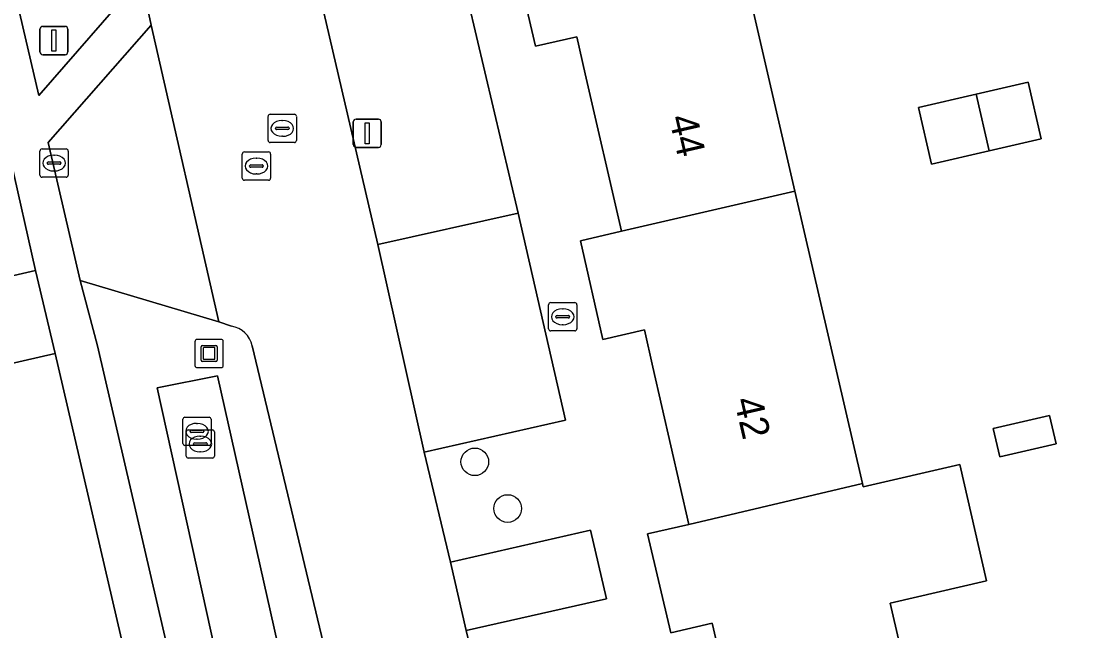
# Model space of a CAD drawing. Extents: x 156412 to 157779, y 382335 to 383768.
# Drawn here: x 156911.01 to 156948.58, y 382902.2 to 382923.76 of the extents above; entities that cross this region are included whole.
import ezdxf

# ---------------------------------------------------------------- set-up
doc = ezdxf.new("R2010")
doc.units = 0
for name, color, linetype in [('IMGEO_Berm_groen', 7, 'Continuous'), ('IMGEO_Boom', 7, 'Continuous'), ('IMGEO_Brandkraan', 7, 'Continuous'), ('IMGEO_Erf', 7, 'Continuous'), ('IMGEO_Greppel_droge_sloot', 7, 'Continuous'), ('IMGEO_Kolk', 7, 'Continuous'), ('IMGEO_Kunstobject', 7, 'Continuous'), ('IMGEO_Lichtmast', 7, 'Continuous'), ('IMGEO_Pand', 7, 'Continuous'), ('IMGEO_Pand_nummerreeks', 7, 'Continuous'), ('IMGEO_Parkeervlak_open', 7, 'Continuous'), ('IMGEO_Rijbaan_lokaal_gesloten', 7, 'Continuous'), ('IMGEO_Rijbaan_lokaal_open', 7, 'Continuous'), ('IMGEO_Rioolput', 7, 'Continuous'), ('IMGEO_Verkeersbordpaal', 7, 'Continuous'), ('IMGEO_Voetpad_open', 7, 'Continuous')]:
    doc.layers.add(name, color=color, linetype=linetype)

msp = doc.modelspace()

# ---------------------------------------------------------------- linework, layer by layer
at = {"layer": 'IMGEO_Berm_groen'}
for points in [[(156911.7, 382945.268), (156910.613, 382951.316), (156910.458, 382952.176), (156904.698, 382950.847), (156911.631, 382921.128), (156915.25, 382925.291), (156915.615, 382925.675)], [(156918.446, 382912.971), (156917.996, 382913.122), (156913.092, 382914.594), (156913.71, 382912.282), (156918.396, 382892.022), (156918.921, 382892.119), (156921.287, 382881.92), (156920.762, 382881.795), (156925.852, 382859.789), (156930.181, 382860.808)], [(156922.418, 382898.725), (156919.179, 382912.277)]]:
    msp.add_lwpolyline(points, dxfattribs=at)
for points in [[(156926.514, 382925.73), (156921.59, 382924.592), (156923.616, 382915.861), (156928.578, 382916.965)], [(156928.493, 382863.788), (156926.278, 382863.313), (156915.815, 382910.793), (156917.946, 382911.213), (156924.219, 382883.281)]]:
    msp.add_lwpolyline(points, close=True, dxfattribs=at)
msp.add_arc((156918.308, 382912.091), 0.891, 12.0707, 81.0603, dxfattribs=at)
at = {"layer": 'IMGEO_Boom'}
for centre in [(156927.048, 382908.173), (156928.21, 382906.521)]:
    msp.add_circle(centre, 0.489, dxfattribs=at)
at = {"layer": 'IMGEO_Brandkraan'}
for p, q in [((156929.657, 382912.879), (156929.657, 382913.731)), ((156929.732, 382913.805), (156930.584, 382913.805)), ((156930.145, 382913.585), (156930.17, 382913.585)), ((156930.658, 382913.731), (156930.658, 382912.879)), ((156929.916, 382913.299), (156929.916, 382913.311)), ((156930.354, 382913.262), (156929.956, 382913.262)), ((156929.959, 382913.348), (156930.357, 382913.348)), ((156930.4, 382913.311), (156930.4, 382913.299)), ((156930.584, 382912.805), (156929.732, 382912.805)), ((156930.168, 382913.025), (156930.143, 382913.025))]:
    msp.add_line(p, q, dxfattribs=at)
for points in [[(156929.657, 382912.879), (156929.657, 382913.731)], [(156929.732, 382913.805), (156930.584, 382913.805)], [(156930.658, 382913.731), (156930.658, 382912.879)], [(156930.584, 382912.805), (156929.732, 382912.805)]]:
    msp.add_lwpolyline(points, dxfattribs=at)
for centre, radius, start, end in [((156929.734, 382913.729), 0.0765, 91.552, 178.448), ((156929.734, 382913.729), 0.0765, 91.552, 178.448), ((156930.582, 382913.729), 0.0765, 1.552, 88.448), ((156930.582, 382913.729), 0.0765, 1.552, 88.448), ((156929.956, 382913.308), 0.0403, 85.8775, 175.7526), ((156929.953, 382913.298), 0.0366, 178.938, 274.7102), ((156930.357, 382913.305), 0.043, 264.8664, 352.4533), ((156930.361, 382913.31), 0.0386, 1.7309, 96.639), ((156929.734, 382912.881), 0.0765, 181.552, 268.448), ((156929.734, 382912.881), 0.0765, 181.552, 268.448), ((156930.582, 382912.881), 0.0765, 271.552, 358.448), ((156930.582, 382912.881), 0.0765, 271.552, 358.448)]:
    msp.add_arc(centre, radius, start, end, dxfattribs=at)
for centre, major_axis, ratio, start_param, end_param in [((156930.144, 382913.305), (-0.387, 0.002), 0.722429, 4.712389, 7.853982), ((156930.169, 382913.305), (-0.39, 0.002), 0.717154, 1.570796, 4.712389)]:
    msp.add_ellipse(centre, major_axis=major_axis, ratio=ratio, start_param=start_param, end_param=end_param, dxfattribs=at)
at = {"layer": 'IMGEO_Erf'}
for points in [[(156935.969, 382928.126), (156938.368, 382917.746), (156940.758, 382907.406), (156940.785, 382907.289), (156944.196, 382908.075), (156945.146, 382903.963), (156941.735, 382903.177), (156943.161, 382897.01), (156943.188, 382896.893), (156946.598, 382897.679), (156947.546, 382893.577), (156944.136, 382892.791), (156945.561, 382886.624), (156947.96, 382876.242), (156949.418, 382869.934)], [(156908.806, 382911.227), (156912.205, 382912.006), (156911.516, 382914.937), (156840.966, 382898.64)]]:
    msp.add_lwpolyline(points, dxfattribs=at)
for points in [[(156944.779, 382921.175), (156946.618, 382921.6), (156947.08, 382919.601), (156945.24, 382919.176), (156943.196, 382918.703), (156942.734, 382920.703)], [(156945.381, 382909.348), (156947.376, 382909.809), (156947.608, 382908.805), (156945.613, 382908.344)]]:
    msp.add_lwpolyline(points, close=True, dxfattribs=at)
at = {"layer": 'IMGEO_Greppel_droge_sloot'}
msp.add_lwpolyline([(156917.946, 382911.213), (156915.815, 382910.793), (156926.278, 382863.313), (156928.493, 382863.788), (156924.219, 382883.281)], close=True, dxfattribs=at)
at = {"layer": 'IMGEO_Kolk'}
for p, q in [((156916.799, 382909.753), (156917.651, 382909.753)), ((156916.724, 382908.827), (156916.724, 382909.679)), ((156917.212, 382909.533), (156917.237, 382909.533)), ((156917.725, 382909.679), (156917.725, 382908.827)), ((156916.842, 382908.378), (156916.842, 382909.23)), ((156916.917, 382909.304), (156917.769, 382909.304)), ((156916.983, 382909.247), (156916.983, 382909.259)), ((156917.421, 382909.21), (156917.023, 382909.21)), ((156917.026, 382909.296), (156917.424, 382909.296)), ((156917.235, 382908.973), (156917.21, 382908.973)), ((156917.33, 382909.084), (156917.355, 382909.084)), ((156917.467, 382909.259), (156917.467, 382909.247)), ((156917.843, 382909.23), (156917.843, 382908.378)), ((156917.651, 382908.753), (156916.799, 382908.753)), ((156917.101, 382908.798), (156917.101, 382908.81)), ((156917.539, 382908.761), (156917.141, 382908.761)), ((156917.144, 382908.847), (156917.542, 382908.847)), ((156917.585, 382908.81), (156917.585, 382908.798)), ((156917.769, 382908.304), (156916.917, 382908.304)), ((156917.353, 382908.524), (156917.328, 382908.524))]:
    msp.add_line(p, q, dxfattribs=at)
for points in [[(156916.799, 382909.753), (156917.651, 382909.753)], [(156916.724, 382908.827), (156916.724, 382909.679)], [(156917.725, 382909.679), (156917.725, 382908.827)], [(156916.842, 382908.378), (156916.842, 382909.23)], [(156916.917, 382909.304), (156917.769, 382909.304)], [(156917.843, 382909.23), (156917.843, 382908.378)], [(156917.651, 382908.753), (156916.799, 382908.753)], [(156917.769, 382908.304), (156916.917, 382908.304)]]:
    msp.add_lwpolyline(points, dxfattribs=at)
for centre, radius, start, end in [((156916.801, 382909.677), 0.0765, 91.552, 178.448), ((156916.801, 382909.677), 0.0765, 91.552, 178.448), ((156917.649, 382909.677), 0.0765, 1.552, 88.448), ((156917.649, 382909.677), 0.0765, 1.552, 88.448), ((156916.919, 382909.228), 0.0765, 91.552, 178.448), ((156916.919, 382909.228), 0.0765, 91.552, 178.448), ((156917.023, 382909.256), 0.0403, 85.8775, 175.7526), ((156917.02, 382909.246), 0.0366, 178.938, 274.7102), ((156917.424, 382909.253), 0.043, 264.8664, 352.4533), ((156917.428, 382909.258), 0.0386, 1.7309, 96.639), ((156917.767, 382909.228), 0.0765, 1.552, 88.448), ((156917.767, 382909.228), 0.0765, 1.552, 88.448), ((156916.801, 382908.829), 0.0765, 181.552, 268.448), ((156916.801, 382908.829), 0.0765, 181.552, 268.448), ((156917.141, 382908.807), 0.0403, 85.8775, 175.7526), ((156917.138, 382908.797), 0.0366, 178.938, 274.7102), ((156917.542, 382908.804), 0.043, 264.8664, 352.4533), ((156917.546, 382908.809), 0.0386, 1.7309, 96.639), ((156917.649, 382908.829), 0.0765, 271.552, 358.448), ((156917.649, 382908.829), 0.0765, 271.552, 358.448), ((156916.919, 382908.38), 0.0765, 181.552, 268.448), ((156916.919, 382908.38), 0.0765, 181.552, 268.448), ((156917.767, 382908.38), 0.0765, 271.552, 358.448), ((156917.767, 382908.38), 0.0765, 271.552, 358.448)]:
    msp.add_arc(centre, radius, start, end, dxfattribs=at)
for centre, major_axis, ratio, start_param, end_param in [((156917.211, 382909.253), (-0.387, 0.002), 0.722429, 4.712389, 7.853982), ((156917.236, 382909.253), (-0.39, 0.002), 0.717154, 1.570796, 4.712389), ((156917.329, 382908.804), (-0.387, 0.002), 0.722429, 4.712389, 7.853982), ((156917.354, 382908.804), (-0.39, 0.002), 0.717154, 1.570796, 4.712389)]:
    msp.add_ellipse(centre, major_axis=major_axis, ratio=ratio, start_param=start_param, end_param=end_param, dxfattribs=at)
at = {"layer": 'IMGEO_Kunstobject'}
for p, q in [((156917.152, 382912.422), (156917.152, 382911.581)), ((156917.152, 382912.422), (156917.152, 382911.581)), ((156918.068, 382912.506), (156917.227, 382912.506)), ((156918.068, 382912.506), (156917.227, 382912.506)), ((156918.152, 382911.59), (156918.152, 382912.431)), ((156918.152, 382911.59), (156918.152, 382912.431)), ((156917.366, 382911.77), (156917.366, 382912.244)), ((156917.416, 382912.294), (156917.89, 382912.294)), ((156917.446, 382912.194), (156917.446, 382911.82)), ((156917.84, 382912.214), (156917.466, 382912.214)), ((156917.86, 382911.82), (156917.86, 382912.194)), ((156917.94, 382912.244), (156917.94, 382911.77)), ((156917.89, 382911.72), (156917.416, 382911.72)), ((156917.466, 382911.8), (156917.84, 382911.8)), ((156917.236, 382911.506), (156918.077, 382911.506)), ((156917.236, 382911.506), (156918.077, 382911.506))]:
    msp.add_line(p, q, dxfattribs=at)
for centre, radius, start, end in [((156917.23, 382912.428), 0.0779, 92.4484, 184.2845), ((156917.23, 382912.428), 0.0779, 92.4484, 184.2845), ((156918.074, 382912.428), 0.0779, 2.4484, 94.2845), ((156918.074, 382912.428), 0.0779, 2.4484, 94.2845), ((156917.416, 382912.244), 0.05, 90, 180), ((156917.466, 382912.194), 0.02, 90, 180), ((156917.84, 382912.194), 0.02, 360, 90), ((156917.89, 382912.244), 0.05, 360, 90), ((156917.416, 382911.77), 0.05, 180, 270), ((156917.466, 382911.82), 0.02, 180, 270), ((156917.84, 382911.82), 0.02, 270, 0), ((156917.89, 382911.77), 0.05, 270, 0), ((156917.23, 382911.584), 0.0779, 182.4484, 274.2845), ((156917.23, 382911.584), 0.0779, 182.4484, 274.2845), ((156918.074, 382911.584), 0.0779, 272.4484, 4.2845), ((156918.074, 382911.584), 0.0779, 272.4484, 4.2845)]:
    msp.add_arc(centre, radius, start, end, dxfattribs=at)
at = {"layer": 'IMGEO_Lichtmast'}
for p, q in [((156922.848, 382920.297), (156923.638, 382920.297)), ((156923.638, 382920.297), (156922.848, 382920.297)), ((156922.748, 382919.397), (156922.748, 382920.197)), ((156922.748, 382920.197), (156922.748, 382919.397)), ((156923.738, 382920.197), (156923.738, 382919.397)), ((156923.738, 382919.397), (156923.738, 382920.197)), ((156923.638, 382919.297), (156922.848, 382919.297)), ((156922.848, 382919.297), (156923.638, 382919.297))]:
    msp.add_line(p, q, dxfattribs=at)
msp.add_lwpolyline([(156923.168, 382920.172), (156923.318, 382920.172), (156923.318, 382919.422), (156923.168, 382919.422), (156923.168, 382920.172)], dxfattribs=at)
for centre, start, end in [((156922.848, 382920.197), 90, 180), ((156922.848, 382920.197), 90, 180), ((156923.638, 382920.197), 0, 90), ((156923.638, 382920.197), 360, 90), ((156922.848, 382919.397), 180, 270), ((156922.848, 382919.397), 180, 270), ((156923.638, 382919.397), 270, 0), ((156923.638, 382919.397), 270, 0)]:
    msp.add_arc(centre, 0.1, start, end, dxfattribs=at)
at = {"layer": 'IMGEO_Pand'}
for points in [[(156929.849, 382926.712), (156928.384, 382926.373), (156929.194, 382922.874), (156930.652, 382923.212), (156930.955, 382921.896), (156932.236, 382916.329), (156938.368, 382917.746), (156935.969, 382928.126)], [(156944.779, 382921.175), (156945.24, 382919.176), (156947.08, 382919.601), (156946.618, 382921.6)], [(156944.779, 382921.175), (156942.734, 382920.703), (156943.196, 382918.703), (156945.24, 382919.176)], [(156934.621, 382905.958), (156940.758, 382907.406), (156938.368, 382917.746), (156932.236, 382916.329), (156930.781, 382915.995), (156931.58, 382912.506), (156933.049, 382912.842), (156933.349, 382911.526)], [(156903.931, 382907.05), (156906.295, 382896.833), (156915.255, 382898.9), (156912.205, 382912.006), (156908.806, 382911.227), (156909.005, 382910.37), (156906.53, 382909.797), (156907.001, 382907.761)], [(156945.381, 382909.348), (156945.613, 382908.344), (156947.608, 382908.805), (156947.376, 382909.809)], [(156934.621, 382905.958), (156933.16, 382905.629), (156933.98, 382902.125), (156935.442, 382902.467), (156935.745, 382901.152), (156937.027, 382895.58), (156943.161, 382897.01), (156941.735, 382903.177), (156945.146, 382903.963), (156944.196, 382908.075), (156940.785, 382907.289), (156940.758, 382907.406)]]:
    msp.add_lwpolyline(points, close=True, dxfattribs=at)
at = {"layer": 'IMGEO_Parkeervlak_open'}
for points in [[(156923.616, 382915.861), (156925.261, 382908.509), (156930.254, 382909.649), (156928.578, 382916.965)], [(156931.704, 382903.321), (156931.145, 382905.759), (156926.191, 382904.624), (156926.746, 382902.205)]]:
    msp.add_lwpolyline(points, close=True, dxfattribs=at)
at = {"layer": 'IMGEO_Rijbaan_lokaal_gesloten'}
for points in [[(156915.615, 382925.675), (156915.25, 382925.291), (156915.609, 382923.621), (156917.996, 382913.122), (156918.446, 382912.971)], [(156935.752, 382863.214), (156934.622, 382868.06), (156934.136, 382870.145), (156933.016, 382874.979), (156932.721, 382876.333), (156931.57, 382881.247), (156931.32, 382882.368), (156930.22, 382887.222), (156929.616, 382889.799), (156928.505, 382894.672), (156928.138, 382896.285), (156927.28, 382899.952), (156927.014, 382901.089), (156926.746, 382902.205), (156926.191, 382904.624), (156925.261, 382908.509), (156923.616, 382915.861), (156921.59, 382924.592)], [(156919.179, 382912.277), (156922.418, 382898.725), (156929.898, 382865.604), (156930.667, 382860.901)]]:
    msp.add_lwpolyline(points, dxfattribs=at)
msp.add_arc((156918.308, 382912.091), 0.891, 12.0707, 81.0603, dxfattribs=at)
at = {"layer": 'IMGEO_Rijbaan_lokaal_open'}
msp.add_lwpolyline([(156915.609, 382923.621), (156911.966, 382919.466), (156913.092, 382914.594), (156917.996, 382913.122)], close=True, dxfattribs=at)
msp.add_lwpolyline([(156837.115, 382897.607), (156838.598, 382897.917), (156840.966, 382898.64), (156911.516, 382914.937), (156910.626, 382918.883), (156910.514, 382919.415), (156764.262, 382885.667), (156691.253, 382868.836), (156691.37, 382868.246), (156689.34, 382868.448), (156683.638, 382869.423)], dxfattribs=at)
at = {"layer": 'IMGEO_Rioolput'}
for p, q in [((156919.74, 382919.544), (156919.74, 382920.396)), ((156919.815, 382920.47), (156920.667, 382920.47)), ((156920.228, 382920.25), (156920.253, 382920.25)), ((156920.741, 382920.396), (156920.741, 382919.544)), ((156919.999, 382919.964), (156919.999, 382919.976)), ((156920.437, 382919.927), (156920.039, 382919.927)), ((156920.042, 382920.013), (156920.44, 382920.013)), ((156920.483, 382919.976), (156920.483, 382919.964)), ((156920.251, 382919.69), (156920.226, 382919.69)), ((156911.671, 382918.316), (156911.671, 382919.168)), ((156911.746, 382919.242), (156912.598, 382919.242)), ((156912.672, 382919.168), (156912.672, 382918.316)), ((156918.902, 382919.136), (156919.754, 382919.136)), ((156920.667, 382919.47), (156919.815, 382919.47)), ((156911.93, 382918.736), (156911.93, 382918.748)), ((156911.973, 382918.785), (156912.371, 382918.785)), ((156912.159, 382919.022), (156912.184, 382919.022)), ((156912.414, 382918.748), (156912.414, 382918.736)), ((156918.827, 382918.21), (156918.827, 382919.062)), ((156919.315, 382918.916), (156919.34, 382918.916)), ((156919.828, 382919.062), (156919.828, 382918.21)), ((156912.368, 382918.699), (156911.97, 382918.699)), ((156912.182, 382918.462), (156912.157, 382918.462)), ((156919.086, 382918.63), (156919.086, 382918.642)), ((156919.524, 382918.593), (156919.126, 382918.593)), ((156919.129, 382918.679), (156919.527, 382918.679)), ((156919.57, 382918.642), (156919.57, 382918.63)), ((156912.598, 382918.242), (156911.746, 382918.242)), ((156919.754, 382918.136), (156918.902, 382918.136)), ((156919.338, 382918.356), (156919.313, 382918.356))]:
    msp.add_line(p, q, dxfattribs=at)
for points in [[(156919.74, 382919.544), (156919.74, 382920.396)], [(156919.815, 382920.47), (156920.667, 382920.47)], [(156920.741, 382920.396), (156920.741, 382919.544)], [(156911.671, 382918.316), (156911.671, 382919.168)], [(156911.746, 382919.242), (156912.598, 382919.242)], [(156912.672, 382919.168), (156912.672, 382918.316)], [(156918.902, 382919.136), (156919.754, 382919.136)], [(156920.667, 382919.47), (156919.815, 382919.47)], [(156918.827, 382918.21), (156918.827, 382919.062)], [(156919.828, 382919.062), (156919.828, 382918.21)], [(156912.598, 382918.242), (156911.746, 382918.242)], [(156919.754, 382918.136), (156918.902, 382918.136)]]:
    msp.add_lwpolyline(points, dxfattribs=at)
for centre, radius, start, end in [((156919.817, 382920.394), 0.0765, 91.552, 178.448), ((156919.817, 382920.394), 0.0765, 91.552, 178.448), ((156920.665, 382920.394), 0.0765, 1.552, 88.448), ((156920.665, 382920.394), 0.0765, 1.552, 88.448), ((156920.039, 382919.973), 0.0403, 85.8775, 175.7526), ((156920.036, 382919.963), 0.0366, 178.938, 274.7102), ((156920.44, 382919.97), 0.043, 264.8664, 352.4533), ((156920.444, 382919.975), 0.0386, 1.7309, 96.639), ((156919.817, 382919.546), 0.0765, 181.552, 268.448), ((156919.817, 382919.546), 0.0765, 181.552, 268.448), ((156920.665, 382919.546), 0.0765, 271.552, 358.448), ((156920.665, 382919.546), 0.0765, 271.552, 358.448), ((156911.748, 382919.166), 0.0765, 91.552, 178.448), ((156911.748, 382919.166), 0.0765, 91.552, 178.448), ((156912.596, 382919.166), 0.0765, 1.552, 88.448), ((156912.596, 382919.166), 0.0765, 1.552, 88.448), ((156918.904, 382919.06), 0.0765, 91.552, 178.448), ((156918.904, 382919.06), 0.0765, 91.552, 178.448), ((156919.752, 382919.06), 0.0765, 1.552, 88.448), ((156919.752, 382919.06), 0.0765, 1.552, 88.448), ((156911.97, 382918.745), 0.0403, 85.8775, 175.7526), ((156912.375, 382918.747), 0.0386, 1.7309, 96.639), ((156911.967, 382918.735), 0.0366, 178.938, 274.7102), ((156912.371, 382918.742), 0.043, 264.8664, 352.4533), ((156919.126, 382918.639), 0.0403, 85.8775, 175.7526), ((156919.123, 382918.629), 0.0366, 178.938, 274.7102), ((156919.527, 382918.636), 0.043, 264.8664, 352.4533), ((156919.531, 382918.641), 0.0386, 1.7309, 96.639), ((156911.748, 382918.318), 0.0765, 181.552, 268.448), ((156911.748, 382918.318), 0.0765, 181.552, 268.448), ((156912.596, 382918.318), 0.0765, 271.552, 358.448), ((156912.596, 382918.318), 0.0765, 271.552, 358.448), ((156918.904, 382918.212), 0.0765, 181.552, 268.448), ((156918.904, 382918.212), 0.0765, 181.552, 268.448), ((156919.752, 382918.212), 0.0765, 271.552, 358.448), ((156919.752, 382918.212), 0.0765, 271.552, 358.448)]:
    msp.add_arc(centre, radius, start, end, dxfattribs=at)
for centre, major_axis, ratio, start_param, end_param in [((156920.227, 382919.97), (-0.387, 0.002), 0.722429, 4.712389, 7.853982), ((156920.252, 382919.97), (-0.39, 0.002), 0.717154, 1.570796, 4.712389), ((156912.158, 382918.742), (-0.387, 0.002), 0.722429, 4.712389, 7.853982), ((156912.183, 382918.742), (-0.39, 0.002), 0.717154, 1.570796, 4.712389), ((156919.314, 382918.636), (-0.387, 0.002), 0.722429, 4.712389, 7.853982), ((156919.339, 382918.636), (-0.39, 0.002), 0.717154, 1.570796, 4.712389)]:
    msp.add_ellipse(centre, major_axis=major_axis, ratio=ratio, start_param=start_param, end_param=end_param, dxfattribs=at)
at = {"layer": 'IMGEO_Verkeersbordpaal'}
for p, q in [((156911.668, 382922.677), (156911.668, 382923.477)), ((156911.668, 382923.477), (156911.668, 382922.677)), ((156911.768, 382923.577), (156912.558, 382923.577)), ((156912.558, 382923.577), (156911.768, 382923.577)), ((156912.658, 382923.477), (156912.658, 382922.677)), ((156912.658, 382922.677), (156912.658, 382923.477)), ((156912.558, 382922.577), (156911.768, 382922.577)), ((156911.768, 382922.577), (156912.558, 382922.577))]:
    msp.add_line(p, q, dxfattribs=at)
msp.add_lwpolyline([(156912.088, 382923.452), (156912.238, 382923.452), (156912.238, 382922.702), (156912.088, 382922.702), (156912.088, 382923.452)], dxfattribs=at)
for centre, start, end in [((156911.768, 382923.477), 90, 180), ((156911.768, 382923.477), 90, 180), ((156912.558, 382923.477), 0, 90), ((156912.558, 382923.477), 360, 90), ((156911.768, 382922.677), 180, 270), ((156911.768, 382922.677), 180, 270), ((156912.558, 382922.677), 270, 0), ((156912.558, 382922.677), 270, 0)]:
    msp.add_arc(centre, 0.1, start, end, dxfattribs=at)
at = {"layer": 'IMGEO_Voetpad_open'}
for points in [[(156913.71, 382912.282), (156913.092, 382914.594), (156911.966, 382919.466), (156915.609, 382923.621), (156915.25, 382925.291), (156911.631, 382921.128), (156904.698, 382950.847), (156903.296, 382950.523), (156903.73, 382948.528), (156906.351, 382937.287), (156909.964, 382921.799), (156910.196, 382920.789), (156910.514, 382919.415), (156910.626, 382918.883), (156911.516, 382914.937), (156912.205, 382912.006), (156915.255, 382898.9), (156917.831, 382887.65), (156918.253, 382885.661), (156918.763, 382883.533), (156920.983, 382873.977), (156923.698, 382862.279)], [(156935.745, 382901.152), (156935.442, 382902.467), (156933.98, 382902.125), (156933.16, 382905.629), (156934.621, 382905.958), (156933.349, 382911.526), (156933.049, 382912.842), (156931.58, 382912.506), (156930.781, 382915.995), (156932.236, 382916.329), (156930.955, 382921.896), (156930.652, 382923.212), (156929.194, 382922.874), (156928.384, 382926.373)], [(156926.514, 382925.73), (156928.578, 382916.965), (156930.254, 382909.649), (156925.261, 382908.509), (156926.191, 382904.624), (156931.145, 382905.759), (156931.704, 382903.321), (156926.746, 382902.205), (156927.014, 382901.089)], [(156928.499, 382858.363), (156930.281, 382858.756), (156930.325, 382859.272), (156930.326, 382859.696), (156930.273, 382860.291), (156930.181, 382860.808), (156925.852, 382859.789), (156920.762, 382881.795), (156918.396, 382892.022), (156913.71, 382912.282)]]:
    msp.add_lwpolyline(points, dxfattribs=at)

# ---------------------------------------------------------------- texts
at = {"layer": 'IMGEO_Pand_nummerreeks'}
for s, p in [('44', (156933.907, 382920.349)), ('42', (156936.212, 382910.358))]:
    msp.add_text(s, height=1, rotation=282.9936, dxfattribs=at).set_placement(p)

doc.saveas('drawing.dxf')
